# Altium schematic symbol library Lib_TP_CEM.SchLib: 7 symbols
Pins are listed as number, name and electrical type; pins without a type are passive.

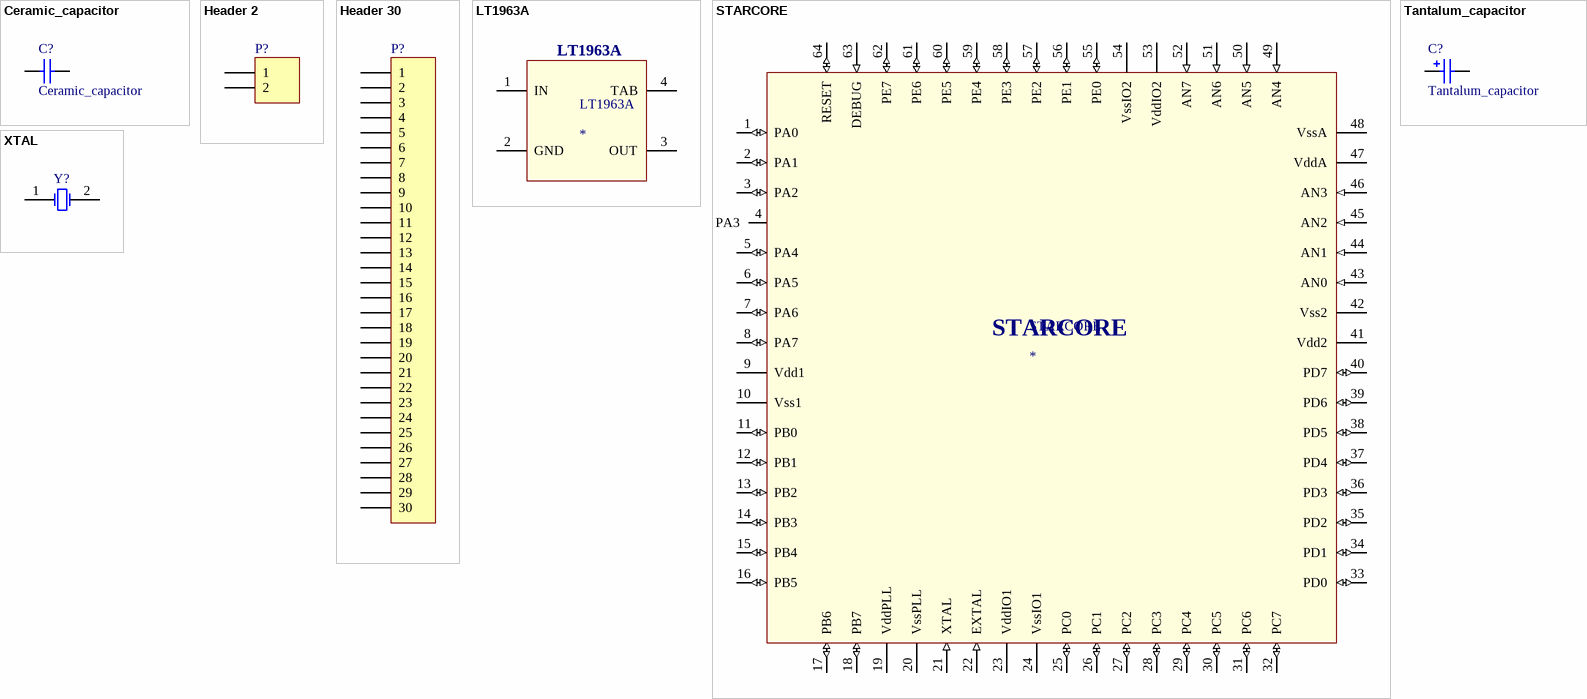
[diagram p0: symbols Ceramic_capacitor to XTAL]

## Ceramic_capacitor
designator C?
SMD Ceramic Capacitor
footprint 0603 (Chip Capacitor; Body 1.6 x 0.8 mm (LxW typ))
pins: 1, 2

## Header 2
designator P?
Header, 2-Pin
footprint Header2
pins: 1, 2

## Header 30
designator P?
Header, 30-Pin
footprint TFM-115-02
pins: 1, 2, 3, 4, 5, 6, 7, 8, 9, 10, 11, 12, 13, 14, 15, 16, 17, 18, 19, 20, 21, 22, 23, 24, 25, 26, 27, 28, 29, 30

## LT1963A
designator LT1963A
LDO Regulator, 2.5 V, 2 A, SOT223
footprint SOT223
footprint SOT223
pins: 1 IN (power) "Input", 2 GND (power) "ground", 3 OUT (power) "Output", 4 TAB (power) "Ground"

## STARCORE
designator STARCORE
STARCORE schematic
footprint QFP64 (STARCORE package)
pins: 1 PA0 (io), 2 PA1 (io), 3 PA2 (io), 4 PA3 (io), 5 PA4 (io), 6 PA5 (io), 7 PA6 (io), 8 PA7 (io), 9 Vdd1 (power) "Core power supply", 10 Vss1 (power) "Core power supply", 11 PB0 (io), 12 PB1 (io), 13 PB2 (io), 14 PB3 (io), 15 PB4 (io), 16 PB5 (io), 17 PB6 (io), 18 PB7 (io), 19 VddPLL (power) "PLL power supply", 20 VssPLL (power) "PLL power supply", 21 XTAL (in), 22 EXTAL (in), 23 VddIO1 (power) "IO power supply", 24 VssIO1 (power) "IO power supply", 25 PC0 (io), 26 PC1 (io), 27 PC2 (io), 28 PC3 (io), 29 PC4 (io), 30 PC5 (io), 31 PC6 (io), 32 PC7 (io), 33 PD0 (io), 34 PD1 (io), 35 PD2 (io), 36 PD3 (io), 37 PD4 (io), 38 PD5 (io), 39 PD6 (io), 40 PD7 (io), 41 Vdd2 (power) "Core power supply", 42 Vss2 (power) "Core power supply", 43 AN0 (in), 44 AN1 (in), 45 AN2 (in), 46 AN3 (in), 47 VddA (power) "Analog power supply", 48 VssA (power) "Analog power supply", 49 AN4 (in), 50 AN5 (in), 51 AN6 (in), 52 AN7 (in), 53 VddIO2 (power) "IO power supply", 54 VssIO2 (power) "IO power supply", 55 PE0 (io), 56 PE1 (io), 57 PE2 (io), 58 PE3 (io), 59 PE4 (io), 60 PE5 (io), 61 PE6 (io), 62 PE7 (io), 63 DEBUG (in), 64 RESET (io)

## Tantalum_capacitor
designator C?
Tantamount Commercial, Surface Mount Solid Tantalum Chip Capacitor: 10uF; Note: See Data Sheet for full range of components; Value: 150uF
footprint 6032 (Capacitor, SM Tantalum; Body 6.0 x 3.2 mm (LxW typ))
pins: 1, 2
1 alternate drawing of the same symbol

## XTAL
designator Y?
Crystal Oscillator
footprint Quartz
pins: 1 OSC1, 2 OSC2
